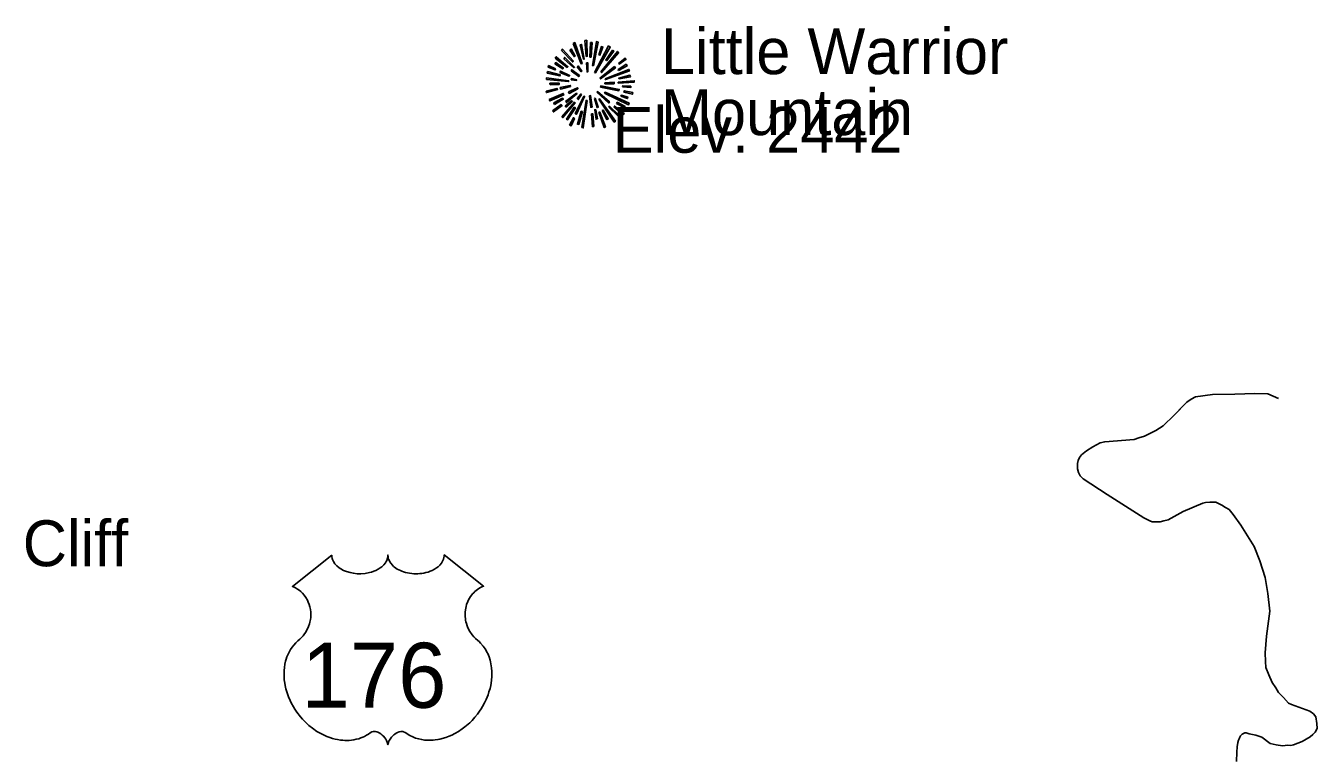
# Model space of a CAD drawing. Extents: x 990631 to 1056237, y 535999 to 585651.
# Drawn here: x 1017463 to 1021687, y 552960 to 555341 of the extents above; entities that cross this region are included whole.
import ezdxf

# ---------------------------------------------------------------- set-up
doc = ezdxf.new("R2010")
doc.units = 0
for name, color, linetype in [('Exist Geographical Mountain Summit CELL', 7, 'Continuous'), ('Exist Geographical Mountain Summit Elevation Number Label', 7, 'Continuous'), ('Exist Geographical Mountain Summit Label', 7, 'Continuous'), ('Exist Road Non-System Type 51', 7, 'Continuous'), ('Exist Road Primary US Shield CELL', 7, 'Continuous'), ('Exist Road Primary US Shield Number Label', 7, 'Continuous')]:
    doc.layers.add(name, color=color, linetype=linetype)

msp = doc.modelspace()

# ---------------------------------------------------------------- linework, layer by layer
at = {"layer": 'Exist Geographical Mountain Summit CELL'}
for points in [[(1019253.4, 555283.9), (1019279.5, 555217), (1019282.5, 555218), (1019258.5, 555286.4)], [(1019287.2, 555231.9), (1019289.7, 555232.6), (1019280.7, 555280.5), (1019276.3, 555279.4)], [(1019291.9, 555293.3), (1019296, 555241.3), (1019299.2, 555241.7), (1019297.8, 555294.3)], [(1019307.9, 555239.2), (1019311.9, 555239.2), (1019315.5, 555286.4), (1019310.1, 555286.4)], [(1019319.9, 555210.8), (1019334.8, 555287.8), (1019329.3, 555289.6), (1019316.6, 555211.5)], [(1019323.2, 555189), (1019326.1, 555187.2), (1019374.7, 555271.8), (1019369.3, 555275.5)], [(1019194.5, 555235.8), (1019234.1, 555205.3), (1019236.3, 555207.5), (1019198.2, 555240.2)], [(1019214.9, 555260.6), (1019250.8, 555223.1), (1019254.2, 555225.7), (1019218.9, 555265.3)], [(1019222.8, 555232.9), (1019255.6, 555203.9), (1019257.8, 555206), (1019225.8, 555238)], [(1019242.5, 555262), (1019258.1, 555240.2), (1019259.9, 555241.7), (1019246.5, 555266)], [(1019337.7, 555246), (1019341, 555244.9), (1019350.4, 555271.8), (1019345.7, 555273.6)], [(1019344.2, 555190.4), (1019346.4, 555188.3), (1019402, 555252.5), (1019398, 555257.3)], [(1019381.7, 555262), (1019360.6, 555228.6), (1019363.5, 555227.5), (1019386, 555258.8)], [(1019402, 555218.4), (1019403.9, 555215.9), (1019426.7, 555232.2), (1019423.1, 555235.8)], [(1019168.7, 555186.8), (1019210.1, 555177.3), (1019211.3, 555180.6), (1019169.8, 555191.5)], [(1019171.7, 555206), (1019194.1, 555197.3), (1019195.2, 555200.3), (1019173.1, 555211.2)], [(1019193.4, 555217), (1019219.2, 555200.6), (1019221.4, 555203.2), (1019196.3, 555220.9)], [(1019210.1, 555189), (1019240.7, 555177), (1019241.8, 555179.1), (1019212.3, 555193)], [(1019246.5, 555194.4), (1019271.6, 555175.5), (1019273.7, 555178.4), (1019249, 555197.7)], [(1019266.1, 555207.5), (1019279.9, 555191.1), (1019282.1, 555193.3), (1019269.4, 555210.4)], [(1019297.4, 555219.9), (1019298.8, 555190.8), (1019301.4, 555191.1), (1019301.4, 555220.2)], [(1019341, 555170.4), (1019342.8, 555167.9), (1019391.4, 555203.9), (1019388.2, 555208.2)], [(1019358, 555167.6), (1019359.1, 555165.3), (1019437.3, 555194), (1019435.5, 555198.8)], [(1019402, 555195.5), (1019429.6, 555210.4), (1019426.7, 555215.5), (1019400.6, 555198.1)], [(1019166.1, 555165.7), (1019238.1, 555158.8), (1019238.5, 555161.7), (1019166.1, 555170.8)], [(1019178.2, 555148.3), (1019207.9, 555149.7), (1019207.9, 555153.3), (1019177.1, 555153.3)], [(1019246.8, 555164.6), (1019263.9, 555162.4), (1019264.3, 555164.6), (1019247.6, 555169)], [(1019357, 555154.9), (1019357, 555151.9), (1019387.1, 555151.9), (1019387.8, 555157)], [(1019400.2, 555153.7), (1019452.6, 555157), (1019452.9, 555161.7), (1019400.6, 555157)], [(1019403.9, 555167.6), (1019440.6, 555174.1), (1019439.1, 555179.5), (1019402.4, 555169.8)], [(1019164.7, 555127.9), (1019166.1, 555122.8), (1019202.2, 555133.4), (1019200, 555136.6)], [(1019174.5, 555100.3), (1019177.1, 555095.6), (1019222.5, 555115.6), (1019221, 555120.3)], [(1019210.5, 555139.2), (1019211.6, 555134.5), (1019244.7, 555142.8), (1019244, 555146.5)], [(1019228.3, 555093.8), (1019231.2, 555090.1), (1019265.7, 555118.5), (1019263.9, 555121)], [(1019238.1, 555125), (1019240.3, 555120.3), (1019269.1, 555135.5), (1019268, 555138.8)], [(1019259.9, 555053.8), (1019264.3, 555052), (1019290.8, 555110.4), (1019288.3, 555111.2)], [(1019266.8, 555103.2), (1019270.1, 555100.3), (1019280.3, 555116.6), (1019278.4, 555118.1)], [(1019306.8, 555112.3), (1019310.8, 555075.3), (1019315.2, 555075.6), (1019310.1, 555113)], [(1019331.2, 555123.9), (1019369.7, 555088.7), (1019372.2, 555093), (1019333, 555126.1)], [(1019342.4, 555141), (1019403.1, 555129.1), (1019404.2, 555133.4), (1019343.5, 555144.6)], [(1019356.2, 555121.4), (1019434.4, 555083.2), (1019436.2, 555088.7), (1019357.7, 555124.3)], [(1019409.7, 555111.2), (1019430.7, 555103.2), (1019432.5, 555107.6), (1019411.1, 555114.4)], [(1019415.1, 555141.8), (1019441.6, 555139.5), (1019441.6, 555143.9), (1019415.5, 555145)], [(1019419.2, 555124.6), (1019447.4, 555117.4), (1019448.2, 555122.8), (1019420.2, 555129.1)], [(1019185.8, 555063.6), (1019188.7, 555059.6), (1019217.1, 555080.7), (1019214.5, 555083.9)], [(1019192, 555084.3), (1019221, 555101), (1019218.9, 555104.7), (1019189.8, 555089.4)], [(1019216.7, 555044), (1019219.6, 555041.4), (1019260.3, 555089.1), (1019257.4, 555091.2)], [(1019232, 555075.3), (1019251.2, 555093.4), (1019247.9, 555095.6), (1019227.6, 555078.5)], [(1019256.7, 555075.3), (1019231.6, 555036), (1019234.8, 555033.5), (1019260.7, 555073)], [(1019281.3, 555008.4), (1019286.1, 555007.3), (1019298.8, 555096.6), (1019295.6, 555097.4)], [(1019322.8, 555103.6), (1019331.5, 555073.8), (1019335.5, 555075.6), (1019325, 555104.7)], [(1019332.6, 555037.1), (1019327.2, 555066.9), (1019323.9, 555066.9), (1019328.3, 555036)], [(1019337.3, 555101.4), (1019387.8, 555026.5), (1019391.4, 555029.4), (1019339.9, 555102.5)], [(1019347.8, 555064.3), (1019363.8, 555034.9), (1019367.9, 555037.1), (1019351.6, 555065.8)], [(1019369.7, 555075.6), (1019399.8, 555046.5), (1019403.1, 555049.1), (1019371.9, 555078.1)], [(1019386.4, 555076.3), (1019416.9, 555050.5), (1019420.2, 555054.1), (1019388.2, 555078.9)], [(1019395.5, 555087.3), (1019420.6, 555074.2), (1019423.1, 555077.8), (1019397.7, 555091.2)], [(1019241.8, 555016.7), (1019246.5, 555013.8), (1019257.4, 555038.5), (1019254.2, 555040.7)], [(1019271.6, 555018.6), (1019283.5, 555061.4), (1019279.9, 555061.8), (1019267.2, 555019.6)], [(1019313, 555053.8), (1019316.6, 555011.3), (1019320.6, 555012.3), (1019317.3, 555053.8)], [(1019337.3, 555058.5), (1019354.8, 555008.7), (1019359.1, 555010.5), (1019340.3, 555059.3)]]:
    msp.add_lwpolyline(points, close=True, dxfattribs=at)
at = {"layer": 'Exist Road Non-System Type 51'}
for points in [[(1021560.9, 554122.9), (1021525.4, 554138.1), (1021483.4, 554139.5), (1021417.3, 554137.6), (1021345.1, 554136.1), (1021288.9, 554128), (1021274.5, 554120.5), (1021260.3, 554111), (1021218.9, 554068.2), (1021183.6, 554033.5), (1021159, 554018.2), (1021122.5, 553999.5), (1021104.1, 553994.1), (1021088, 553988.6), (1020991.9, 553981.8), (1020977.6, 553978.3), (1020953.1, 553965.1), (1020932.6, 553951.8), (1020916.4, 553938.3), (1020910, 553930.4), (1020905.6, 553920.7), (1020903.4, 553910.7), (1020903, 553902.7), (1020902.6, 553892.7), (1020906.4, 553880.7), (1020912, 553870.3), (1020921.6, 553860.1), (1021000, 553809.3), (1021119.5, 553733.3), (1021139.3, 553722.7), (1021147.2, 553720.3), (1021155.2, 553720.2), (1021173.2, 553719.6), (1021185.3, 553723.2), (1021199.4, 553726.7), (1021248.3, 553753.1), (1021313.3, 553781), (1021321.3, 553782.7), (1021335.4, 553784.2), (1021355.4, 553783.6), (1021375.2, 553774.8), (1021386.8, 553766.5), (1021398.7, 553760.1), (1021412.2, 553743.6), (1021436.9, 553708.7), (1021480.7, 553639.2), (1021499.2, 553592.6), (1021517.3, 553538), (1021525.6, 553485.6), (1021531.6, 553427.5), (1021521, 553345.7), (1021517.1, 553291.7), (1021518.1, 553263.7), (1021519.5, 553243.7), (1021528.6, 553219.3), (1021540, 553195.1), (1021551.2, 553176.6), (1021560.9, 553162.2), (1021576.4, 553145.7), (1021593.6, 553127.1), (1021603.5, 553122.7), (1021662.9, 553100.7), (1021674.5, 553092.5), (1021682.1, 553082.1), (1021685.5, 553060.1), (1021687, 553044), (1021680.5, 553032.2), (1021672.4, 553024.5), (1021664, 553016.7), (1021637.5, 553001.6), (1021609.1, 552990.6), (1021601, 552988.8), (1021591, 552989.2), (1021573, 552987.7), (1021553, 552990.3), (1021543.1, 552992.7), (1021533.3, 552995.1), (1021505.9, 553015.9), (1021486.1, 553022.7), (1021464.2, 553027.3), (1021454.4, 553029.7), (1021450.4, 553029.8), (1021446.4, 553027.9), (1021442.1, 553026.2), (1021440.1, 553024.2), (1021436, 553020.3), (1021433.9, 553016.3), (1021431.6, 553010.4), (1021429.5, 553006.4), (1021427.4, 552998.7), (1021424.9, 552984.7), (1021424.1, 552966.7), (1021423.1, 552936.7)], [(1021249.1, 554099.4), (1021218.9, 554068.2), (1021183.6, 554033.5), (1021159, 554018.2), (1021122.5, 553999.5), (1021104.1, 553994.1), (1021088, 553988.6), (1020991.9, 553981.8), (1020977.6, 553978.3), (1020953.1, 553965.1), (1020932.6, 553951.8), (1020916.4, 553938.3), (1020910, 553930.4), (1020905.6, 553920.7), (1020903.4, 553910.7), (1020903, 553902.7), (1020902.6, 553892.7), (1020906.4, 553880.7), (1020912, 553870.3), (1020921.6, 553860.1), (1021000, 553809.3), (1021119.5, 553733.3), (1021139.3, 553722.7), (1021147.2, 553720.3), (1021155.2, 553720.2), (1021173.2, 553719.6), (1021185.3, 553723.2), (1021199.4, 553726.7), (1021248.3, 553753.1), (1021249.1, 553753.4)]]:
    msp.add_lwpolyline(points, dxfattribs=at)
at = {"layer": 'Exist Road Primary US Shield CELL'}
msp.add_lwpolyline([(1018463.5, 553611.3), (1018463.8, 553606), (1018465.1, 553599.7), (1018466.1, 553596.4), (1018469.1, 553590.2), (1018473.9, 553582.8), (1018480.7, 553575.6), (1018488.4, 553569.3), (1018493.6, 553565.9), (1018502.3, 553561.2), (1018512.3, 553557), (1018523.4, 553553.8), (1018534.7, 553551.6), (1018547.1, 553550.2), (1018559.3, 553550), (1018572.5, 553551), (1018587.1, 553553.8), (1018593.9, 553555.5), (1018601.4, 553558.1), (1018608.4, 553561), (1018616, 553565.1), (1018622.2, 553569), (1018627, 553572.5), (1018633.8, 553579.1), (1018639.3, 553585.8), (1018641.6, 553589.6), (1018643.5, 553593.3), (1018646.2, 553601), (1018647, 553604.5), (1018647.5, 553611.6), (1018648, 553605.6), (1018648.6, 553601.9), (1018649.6, 553598.2), (1018651.1, 553594.3), (1018653.8, 553588.9), (1018656.9, 553584.3), (1018662.6, 553577.6), (1018666.2, 553574.2), (1018669.4, 553571.5), (1018678.2, 553565.5), (1018688.4, 553560.4), (1018693.4, 553558.2), (1018698.5, 553556.4), (1018705.1, 553554.4), (1018711.8, 553552.8), (1018718.5, 553551.6), (1018725.4, 553550.7), (1018732.3, 553550.1), (1018738, 553550), (1018745, 553550), (1018751.5, 553550.4), (1018758.1, 553551.2), (1018765.4, 553552.4), (1018771.2, 553553.7), (1018779, 553555.7), (1018786, 553558.3), (1018792.1, 553560.9), (1018800.1, 553565.1), (1018806.5, 553569.1), (1018811.3, 553572.9), (1018816.9, 553578.1), (1018822.2, 553584.2), (1018825.3, 553588.7), (1018827.5, 553593.4), (1018829.6, 553598.2), (1018830.8, 553603.4), (1018831.4, 553607.9), (1018831.5, 553611.7), (1018960.1, 553509.3), (1018957.1, 553508.1), (1018950.1, 553504.7), (1018944.6, 553501.4), (1018935.7, 553495.2), (1018931.9, 553491.8), (1018928.1, 553488.2), (1018924.6, 553484.4), (1018921.6, 553480.8), (1018917.8, 553475.7), (1018914.5, 553470.5), (1018911.2, 553464.8), (1018908.8, 553459.8), (1018904.9, 553449.5), (1018903, 553443), (1018901.8, 553437.4), (1018900.3, 553426), (1018899.9, 553420.5), (1018899.9, 553415.1), (1018900.2, 553409.4), (1018900.7, 553403.9), (1018901.7, 553398.2), (1018902.6, 553393.2), (1018904.2, 553387.1), (1018906.5, 553379.9), (1018909.3, 553373), (1018915.2, 553361.8), (1018922.7, 553350.4), (1018928.1, 553344), (1018933.5, 553338.6), (1018941.4, 553331.9), (1018945.7, 553328.1), (1018950.6, 553323.1), (1018958.7, 553313.8), (1018961.9, 553309.4), (1018965.2, 553304.5), (1018968.3, 553299.4), (1018971.3, 553293.9), (1018973.7, 553289.1), (1018978.3, 553278.1), (1018981.6, 553267.4), (1018983.1, 553261.7), (1018985.5, 553249.1), (1018986.4, 553242.9), (1018987.4, 553230.6), (1018987.4, 553215.7), (1018986.3, 553201.6), (1018983.6, 553185.1), (1018981.4, 553175.2), (1018978, 553163.7), (1018974.8, 553153.8), (1018968.9, 553139.1), (1018963.7, 553128.5), (1018956.9, 553116), (1018952.3, 553108.5), (1018946.9, 553100.4), (1018940.1, 553091.2), (1018932.2, 553081.3), (1018922.7, 553070.9), (1018915.1, 553063.2), (1018905, 553054.2), (1018899, 553049.2), (1018890.3, 553042.7), (1018878.5, 553034.8), (1018866.8, 553028), (1018856.8, 553022.9), (1018848, 553019.1), (1018836.6, 553014.8), (1018817.6, 553009.5), (1018810.7, 553008.1), (1018802.5, 553006.9), (1018794.9, 553006.1), (1018787.4, 553005.7), (1018777.4, 553005.7), (1018767.4, 553006.4), (1018758, 553007.8), (1018748.2, 553009.9), (1018738, 553012.9), (1018728.7, 553016.5), (1018719.2, 553021.2), (1018703.3, 553031.2), (1018698.7, 553033.6), (1018696.2, 553034.3), (1018690, 553034.6), (1018684.2, 553033.4), (1018678.3, 553031.1), (1018674.7, 553029.2), (1018670, 553026), (1018666.3, 553023.2), (1018661.9, 553019), (1018658.9, 553015.5), (1018656.6, 553012.7), (1018652.1, 553005.7), (1018650.5, 553002.3), (1018648.8, 552998), (1018647.4, 552991.6), (1018645.3, 552999.7), (1018643, 553005), (1018640.3, 553009.5), (1018637.4, 553013.6), (1018632.9, 553018.7), (1018628.9, 553022.6), (1018624, 553026.6), (1018618.9, 553029.7), (1018614.7, 553031.8), (1018610.9, 553033.3), (1018606.3, 553034.4), (1018602.5, 553034.7), (1018599.4, 553034.6), (1018595.1, 553033.6), (1018589.3, 553029.5), (1018583.8, 553025.7), (1018577.8, 553021.9), (1018570.7, 553018.1), (1018565.4, 553015.7), (1018559.2, 553013.3), (1018551.9, 553010.8), (1018544, 553008.8), (1018535.9, 553007.2), (1018528.7, 553006.1), (1018521.1, 553005.4), (1018514.2, 553005.1), (1018506.9, 553005.2), (1018500.2, 553005.7), (1018492.4, 553006.4), (1018482.6, 553007.9), (1018474.6, 553009.7), (1018466.1, 553012), (1018457.3, 553014.7), (1018448, 553018.3), (1018436.3, 553023.4), (1018428.2, 553027.6), (1018415.3, 553034.9), (1018400.3, 553045.3), (1018389, 553054.5), (1018380.6, 553062.1), (1018368.4, 553074.5), (1018361.2, 553082.6), (1018350, 553097.2), (1018342.7, 553107.8), (1018338.1, 553115.5), (1018331.2, 553128), (1018327.5, 553135.8), (1018322.6, 553147.2), (1018318.8, 553157.6), (1018315.6, 553167.5), (1018313.9, 553173.8), (1018311.4, 553184.8), (1018310, 553192.7), (1018308.5, 553203.4), (1018307.7, 553214.7), (1018307.6, 553225.1), (1018307.8, 553233.8), (1018308.8, 553243.9), (1018310.5, 553254.6), (1018312.6, 553263.8), (1018314.5, 553270.4), (1018317.2, 553278.5), (1018320.8, 553287.4), (1018325, 553295.9), (1018329.1, 553302.9), (1018334.2, 553310.5), (1018339.2, 553317), (1018345.8, 553324.1), (1018352.6, 553330.7), (1018358.9, 553335.8), (1018366.3, 553343.1), (1018370.2, 553347.5), (1018374.9, 553353.6), (1018378.6, 553359.3), (1018381.6, 553364.4), (1018385.5, 553371.9), (1018387.8, 553377.6), (1018390.8, 553386.2), (1018392.3, 553392.3), (1018393.8, 553400.1), (1018394.8, 553407.5), (1018395.1, 553416.7), (1018394.9, 553424.3), (1018393.9, 553433.2), (1018392.3, 553441.7), (1018390.2, 553449.1), (1018387.1, 553457.6), (1018384.1, 553463.9), (1018379.2, 553472.3), (1018373.7, 553480.1), (1018368.1, 553486.5), (1018362.4, 553492.2), (1018356.9, 553496.5), (1018351.7, 553500.2), (1018345.2, 553504.1), (1018338.9, 553507.3), (1018334.9, 553508.9)], close=True, dxfattribs=at)
msp.add_lwpolyline([(1018463.5, 553611.3), (1018463.8, 553606), (1018465.1, 553599.7), (1018466.1, 553596.4), (1018469.1, 553590.2), (1018473.9, 553582.8), (1018480.7, 553575.6), (1018488.4, 553569.3), (1018493.6, 553565.9), (1018502.3, 553561.2), (1018512.3, 553557), (1018523.4, 553553.8), (1018534.7, 553551.6), (1018547.1, 553550.2), (1018559.3, 553550), (1018572.5, 553551), (1018587.1, 553553.8), (1018593.9, 553555.5), (1018601.4, 553558.1), (1018608.4, 553561), (1018616, 553565.1), (1018622.2, 553569), (1018627, 553572.5), (1018633.8, 553579.1), (1018639.3, 553585.8), (1018641.6, 553589.6), (1018643.5, 553593.3), (1018646.2, 553601), (1018647, 553604.5), (1018647.5, 553611.6), (1018648, 553605.6), (1018648.6, 553601.9), (1018649.6, 553598.2), (1018651.1, 553594.3), (1018653.8, 553588.9), (1018656.9, 553584.3), (1018662.6, 553577.6), (1018666.2, 553574.2), (1018669.4, 553571.5), (1018678.2, 553565.5), (1018688.4, 553560.4), (1018693.4, 553558.2), (1018698.5, 553556.4), (1018705.1, 553554.4), (1018711.8, 553552.8), (1018718.5, 553551.6), (1018725.4, 553550.7), (1018732.3, 553550.1), (1018738, 553550), (1018745, 553550), (1018751.5, 553550.4), (1018758.1, 553551.2), (1018765.4, 553552.4), (1018771.2, 553553.7), (1018779, 553555.7), (1018786, 553558.3), (1018792.1, 553560.9), (1018800.1, 553565.1), (1018806.5, 553569.1), (1018811.3, 553572.9), (1018816.9, 553578.1), (1018822.2, 553584.2), (1018825.3, 553588.7), (1018827.5, 553593.4), (1018829.6, 553598.2), (1018830.8, 553603.4), (1018831.4, 553607.9), (1018831.5, 553611.7), (1018960.1, 553509.3), (1018957.1, 553508.1), (1018950.1, 553504.7), (1018944.6, 553501.4), (1018935.7, 553495.2), (1018931.9, 553491.8), (1018928.1, 553488.2), (1018924.6, 553484.4), (1018921.6, 553480.8), (1018917.8, 553475.7), (1018914.5, 553470.5), (1018911.2, 553464.8), (1018908.8, 553459.8), (1018904.9, 553449.5), (1018903, 553443), (1018901.8, 553437.4), (1018900.3, 553426), (1018899.9, 553420.5), (1018899.9, 553415.1), (1018900.2, 553409.4), (1018900.7, 553403.9), (1018901.7, 553398.2), (1018902.6, 553393.2), (1018904.2, 553387.1), (1018906.5, 553379.9), (1018909.3, 553373), (1018915.2, 553361.8), (1018922.7, 553350.4), (1018928.1, 553344), (1018933.5, 553338.6), (1018941.4, 553331.9), (1018945.7, 553328.1), (1018950.6, 553323.1), (1018958.7, 553313.8), (1018961.9, 553309.4), (1018965.2, 553304.5), (1018968.3, 553299.4), (1018971.3, 553293.9), (1018973.7, 553289.1), (1018978.3, 553278.1), (1018981.6, 553267.4), (1018983.1, 553261.7), (1018985.5, 553249.1), (1018986.4, 553242.9), (1018987.4, 553230.6), (1018987.4, 553215.7), (1018986.3, 553201.6), (1018983.6, 553185.1), (1018981.4, 553175.2), (1018978, 553163.7), (1018974.8, 553153.8), (1018968.9, 553139.1), (1018963.7, 553128.5), (1018956.9, 553116), (1018952.3, 553108.5), (1018946.9, 553100.4), (1018940.1, 553091.2), (1018932.2, 553081.3), (1018922.7, 553070.9), (1018915.1, 553063.2), (1018905, 553054.2), (1018899, 553049.2), (1018890.3, 553042.7), (1018878.5, 553034.8), (1018866.8, 553028), (1018856.8, 553022.9), (1018848, 553019.1), (1018836.6, 553014.8), (1018817.6, 553009.5), (1018810.7, 553008.1), (1018802.5, 553006.9), (1018794.9, 553006.1), (1018787.4, 553005.7), (1018777.4, 553005.7), (1018767.4, 553006.4), (1018758, 553007.8), (1018748.2, 553009.9), (1018738, 553012.9), (1018728.7, 553016.5), (1018719.2, 553021.2), (1018703.3, 553031.2), (1018698.7, 553033.6), (1018696.2, 553034.3), (1018690, 553034.6), (1018684.2, 553033.4), (1018678.3, 553031.1), (1018674.7, 553029.2), (1018670, 553026), (1018666.3, 553023.2), (1018661.9, 553019), (1018658.9, 553015.5), (1018656.6, 553012.7), (1018652.1, 553005.7), (1018650.5, 553002.3), (1018648.8, 552998), (1018647.4, 552991.6), (1018645.3, 552999.7), (1018643, 553005), (1018640.3, 553009.5), (1018637.4, 553013.6), (1018632.9, 553018.7), (1018628.9, 553022.6), (1018624, 553026.6), (1018618.9, 553029.7), (1018614.7, 553031.8), (1018610.9, 553033.3), (1018606.3, 553034.4), (1018602.5, 553034.7), (1018599.4, 553034.6), (1018595.1, 553033.6), (1018589.3, 553029.5), (1018583.8, 553025.7), (1018577.8, 553021.9), (1018570.7, 553018.1), (1018565.4, 553015.7), (1018559.2, 553013.3), (1018551.9, 553010.8), (1018544, 553008.8), (1018535.9, 553007.2), (1018528.7, 553006.1), (1018521.1, 553005.4), (1018514.2, 553005.1), (1018506.9, 553005.2), (1018500.2, 553005.7), (1018492.4, 553006.4), (1018482.6, 553007.9), (1018474.6, 553009.7), (1018466.1, 553012), (1018457.3, 553014.7), (1018448, 553018.3), (1018436.3, 553023.4), (1018428.2, 553027.6), (1018415.3, 553034.9), (1018400.3, 553045.3), (1018389, 553054.5), (1018380.6, 553062.1), (1018368.4, 553074.5), (1018361.2, 553082.6), (1018350, 553097.2), (1018342.7, 553107.8), (1018338.1, 553115.5), (1018331.2, 553128), (1018327.5, 553135.8), (1018322.6, 553147.2), (1018318.8, 553157.6), (1018315.6, 553167.5), (1018313.9, 553173.8), (1018311.4, 553184.8), (1018310, 553192.7), (1018308.5, 553203.4), (1018307.7, 553214.7), (1018307.6, 553225.1), (1018307.8, 553233.8), (1018308.8, 553243.9), (1018310.5, 553254.6), (1018312.6, 553263.8), (1018314.5, 553270.4), (1018317.2, 553278.5), (1018320.8, 553287.4), (1018325, 553295.9), (1018329.1, 553302.9), (1018334.2, 553310.5), (1018339.2, 553317), (1018345.8, 553324.1), (1018352.6, 553330.7), (1018358.9, 553335.8), (1018366.3, 553343.1), (1018370.2, 553347.5), (1018374.9, 553353.6), (1018378.6, 553359.3), (1018381.6, 553364.4), (1018385.5, 553371.9), (1018387.8, 553377.6), (1018390.8, 553386.2), (1018392.3, 553392.3), (1018393.8, 553400.1), (1018394.8, 553407.5), (1018395.1, 553416.7), (1018394.9, 553424.3), (1018393.9, 553433.2), (1018392.3, 553441.7), (1018390.2, 553449.1), (1018387.1, 553457.6), (1018384.1, 553463.9), (1018379.2, 553472.3), (1018373.7, 553480.1), (1018368.1, 553486.5), (1018362.4, 553492.2), (1018356.9, 553496.5), (1018351.7, 553500.2), (1018345.2, 553504.1), (1018338.9, 553507.3), (1018334.9, 553508.9)], close=True, dxfattribs=at)

# ---------------------------------------------------------------- texts
at = {"layer": 'Exist Geographical Mountain Summit Elevation Number Label'}
msp.add_text('Elev. 2442', height=150, dxfattribs=at).set_placement((1019382.8, 554926.4))
msp.add_text('Elev. 2442', height=150, dxfattribs=at).set_placement((1019382.8, 554926.4))
at = {"layer": 'Exist Geographical Mountain Summit Label'}
for s, p in [('Little Warrior', (1019540.2, 555183.2)), ('Little Warrior', (1019540.2, 555183.2)), ('Mountain', (1019540.2, 554984)), ('Mountain', (1019540.2, 554984)), ('Cliff', (1017452.9, 553574.7)), ('Cliff', (1017452.9, 553574.7))]:
    msp.add_text(s, height=150, dxfattribs=at).set_placement(p)
at = {"layer": 'Exist Road Primary US Shield Number Label'}
msp.add_text('176', height=212.5, dxfattribs=at).set_placement((1018364.7, 553112))
msp.add_text('176', height=212.5, dxfattribs=at).set_placement((1018364.7, 553112))

doc.saveas('drawing.dxf')
